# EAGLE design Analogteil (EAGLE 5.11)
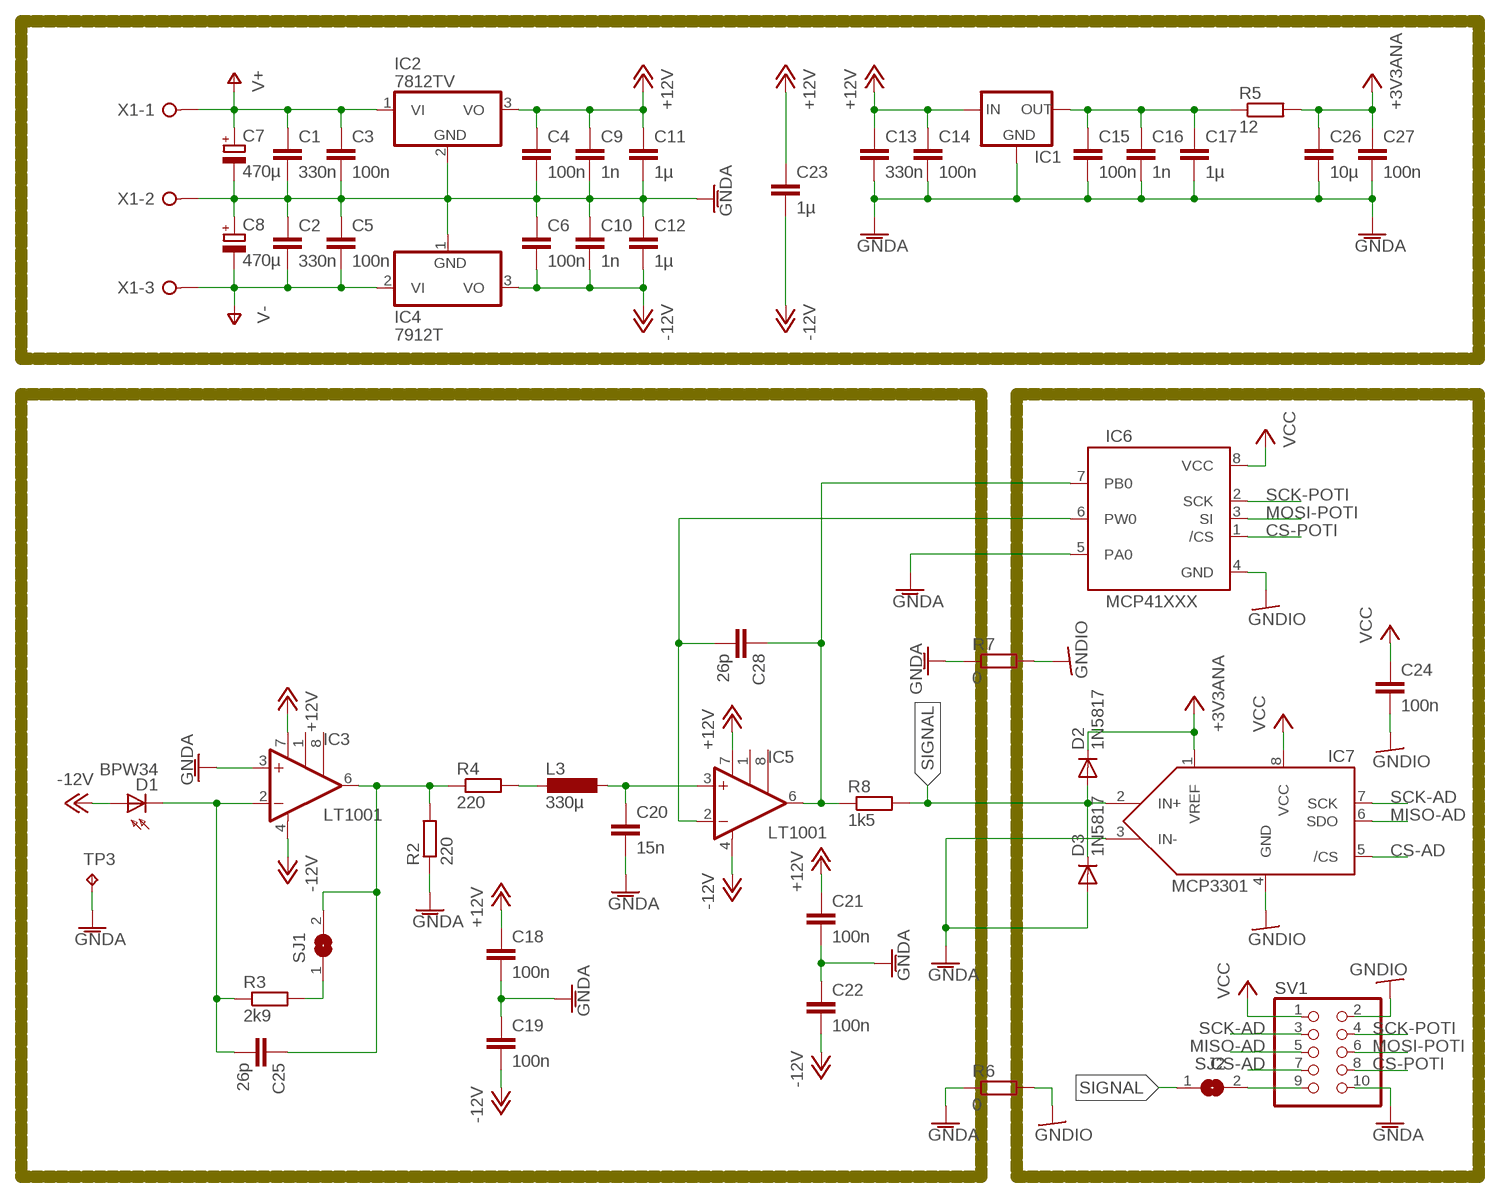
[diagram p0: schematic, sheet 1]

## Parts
C1  330n  C-EU025-024X044  [C025-024X044]
C2  330n  C-EU025-024X044  [C025-024X044]
C3  100n  C-EU025-024X044  [C025-024X044]
C4  100n  C-EU025-024X044  [C025-024X044]
C5  100n  C-EU025-024X044  [C025-024X044]
C6  100n  C-EU025-024X044  [C025-024X044]
C7  470µ  CPOL-EUE3.5-8  [E3,5-8]
C8  470µ  CPOL-EUE3.5-8  [E3,5-8]
C9  1n  C-EU025-024X044  [C025-024X044]
C10  1n  C-EU025-024X044  [C025-024X044]
C11  1µ  C-EU025-024X044  [C025-024X044]
C12  1µ  C-EU025-024X044  [C025-024X044]
C13  330n  C-EU025-024X044  [C025-024X044]
C14  100n  C-EU025-024X044  [C025-024X044]
C15  100n  C-EU025-024X044  [C025-024X044]
C16  1n  C-EU025-024X044  [C025-024X044]
C17  1µ  C-EU025-024X044  [C025-024X044]
C18  100n  C-EU025-024X044  [C025-024X044]
C19  100n  C-EU025-024X044  [C025-024X044]
C20  15n  C-EU025-024X044  [C025-024X044]
C21  100n  C-EU025-024X044  [C025-024X044]
C22  100n  C-EU025-024X044  [C025-024X044]
C23  1µ  C-EU025-024X044  [C025-024X044]
C24  100n  C-EU025-024X044  [C025-024X044]
C25  26p  C-EU025-024X044  [C025-024X044]
C26  10µ  C-EU025-024X044  [C025-024X044]
C27  100n  C-EU025-024X044  [C025-024X044]
C28  26p  C-EU025-024X044  [C025-024X044]
D1  BPW34  BPW32  [BPW32]
D2  1N5817  DIODE-D-2.5  [D-2.5]
D3  1N5817  DIODE-D-2.5  [D-2.5]
IC1  78LXX  [78LXX]
IC2  7812TV  [TO220V]
IC3  LT1001  [DIL08]
IC4  7912T  7912TV  [TO220V]
IC5  LT1001  [DIL08]
IC6  MCP41XXX  [DIL08]
IC7  MCP3301  [DIL08]
L3  330µ  L-EU0204/5  [0204/5]
R2  220  R-EU_0204/2V  [0204V]
R3  2k9  R-EU_0204/2V  [0204V]
R4  220  R-EU_0204/5  [0204/5]
R5  12  R-EU_0204/7  [0204/7]
R6  0  R-EU_0204/2V  [0204V]
R7  0  R-EU_0204/5  [0204/5]
R8  1k5  R-EU_0204/2V  [0204V]
SJ1  SJ  [SJ]
SJ2  SJ  [SJ]
SV1  PINHD-2X05_2.54  [2X05]
TP3  TPPAD1-13  [P1-13]
X1  W237-3E  [W237-3E]

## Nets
+3V3: C26.1 C27.1 D2.C IC7.1(VREF) R5.2 ; supply symbol labelled +3V3ANA
+12V: C4.1 C9.1 C11.1 C13.1 C14.1 C18.1 C21.1 C23.1 IC1.IN IC2.3(VO) IC3.7(V+) IC5.7(V+)
-12V: C6.2 C10.2 C12.2 C19.2 C22.2 C23.2 D1.A IC3.4(V-) IC4.3(VO) IC5.4(V-)
CS-AD: IC7.5(/CS) SV1.7
CS-POTI: IC6.1(/CS) SV1.8
GNDA: C1.2 C2.1 C3.2 C4.2 C5.1 C6.1 C7.- C8.+ C9.2 C10.1 C11.2 C12.1 C13.2 C14.2 C15.2 C16.2 C17.2 C18.2 C19.1 C20.2 C21.2 C22.1 C26.2 C27.2 D3.A IC1.GND IC2.2(GND) IC3.3(+IN) IC4.1(GND) IC6.5(PA0) IC7.3(IN-) R2.1 R6.1 R7.1 SV1.10 TP3.TP X1.2
GNDIO: C24.2 IC6.4(GND) IC7.4(GND) R6.2 R7.2 SV1.2
MISO-AD: IC7.6(SDO) SV1.5
MOSI-POTI: IC6.3(SI) SV1.6
N$1: R3.2 SJ1.1
N$3: SJ2.2 SV1.9
N$6: C25.2 D1.K(C) IC3.2(-IN) R3.1
N$7: C25.1 IC3.6(OUT) R2.2 R4.1 SJ1.2
N$8: L3.2 R4.2
N$9: C20.1 IC5.3(+IN) L3.1
N$10: C28.2 IC5.2(-IN) IC6.6(PW0)
N$11: C15.1 C16.1 C17.1 IC1.OUT R5.1
N$12: C28.1 IC5.6(OUT) IC6.7(PB0) R8.1
SCK-AD: IC7.7(SCK) SV1.3
SCK-POTI: IC6.2(SCK) SV1.4
SIGNAL: D2.A D3.C IC7.2(IN+) R8.2 SJ2.1
V+: C1.1 C3.1 C7.+ IC2.1(VI) X1.1
V-: C2.2 C5.2 C8.- IC4.2(VI) X1.3
VCC: C24.1 IC6.8(VCC) IC7.8(VCC) SV1.1
Unconnected: IC3.1(VOS1) IC3.8(VOS2) IC5.1(VOS1) IC5.8(VOS2)

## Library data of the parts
C1-C6 C9-C27 = resistor:C-EU: CAPACITOR, European symbol
C7 C8 = resistor:CPOL-EU: POLARIZED CAPACITOR, European symbol
C28 = _rcl:C-EU: CAPACITOR, European symbol
D1 = opto-trans-siemens:BPW32: PHOTO DIODE; OC_FARNELL: unknown; OC_NEWARK: unknown
D2 D3 = _mod_diode:DIODE-: DIODE
IC1 = v-reg:78LXX: VOLTAGE REGULATOR
IC2 = linear:78*: Positive VOLTAGE REGULATOR Source: http://cache.national.com/ds/LM/LM78L05.pdf http://www.fairchildsemi.com/ds/LM/LM7805.pdf
IC3 IC5 = _LT100_:LT1001
IC4 = linear:79*: Negative VOLTAGE REGULATOR
IC6 = _LT100_:MCP41XXX
IC7 = _LT100_:MCP3301
L3 = resistor:L-EU: INDUCTOR, European symbol
R2 R5 R7 = resistor:R-EU_: RESISTOR, European symbol
R3 R4 R6 R8 = _rcl:R-EU_: RESISTOR, European symbol
SJ1 SJ2 = jumper:SJ: SMD solder JUMPER
SV1 = _pinhead-2:PINHD-2X05: PIN HEADER
TP3 = testpad:TP: Test pad
X1 = con-wago-508:W237-3E: WAGO SREW CLAMP; OC_FARNELL: unknown; OC_NEWARK: unknown

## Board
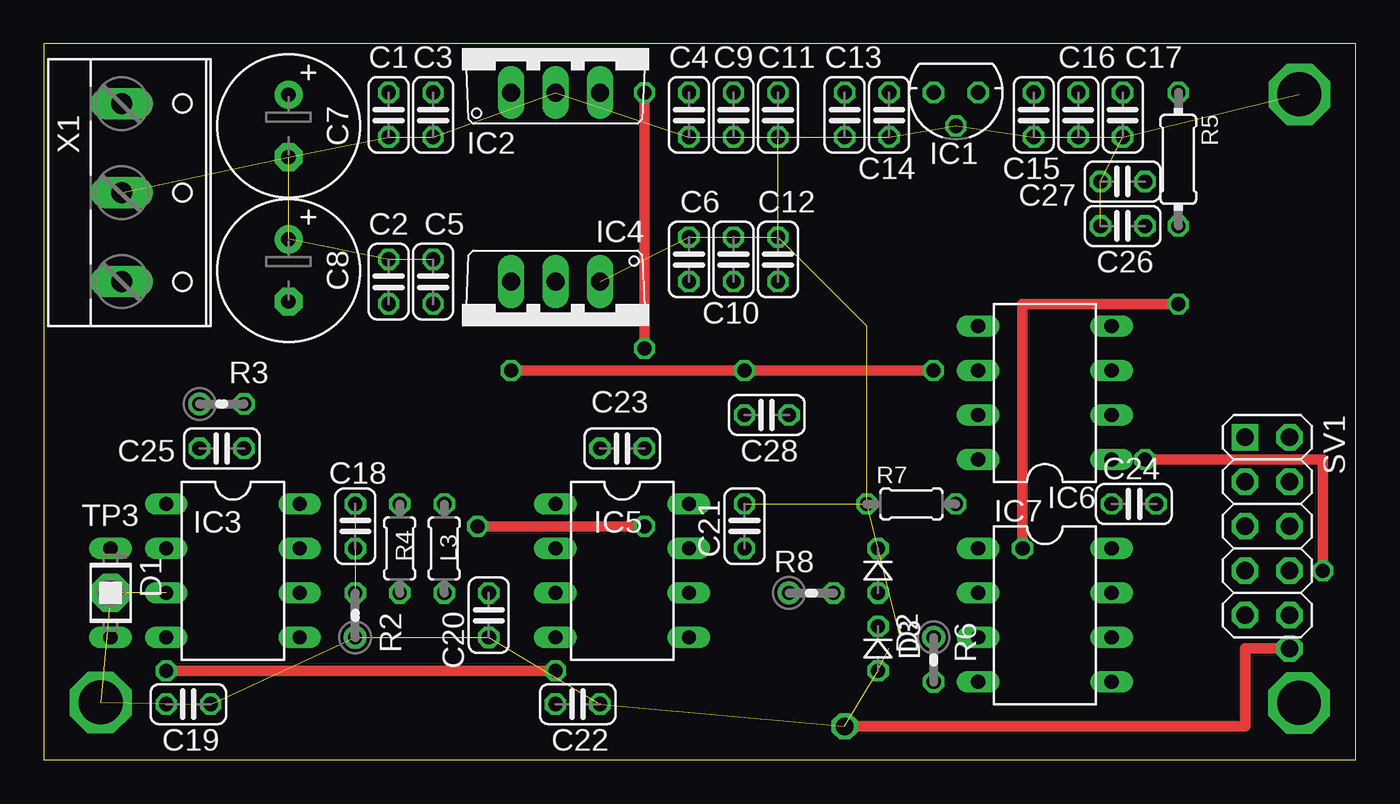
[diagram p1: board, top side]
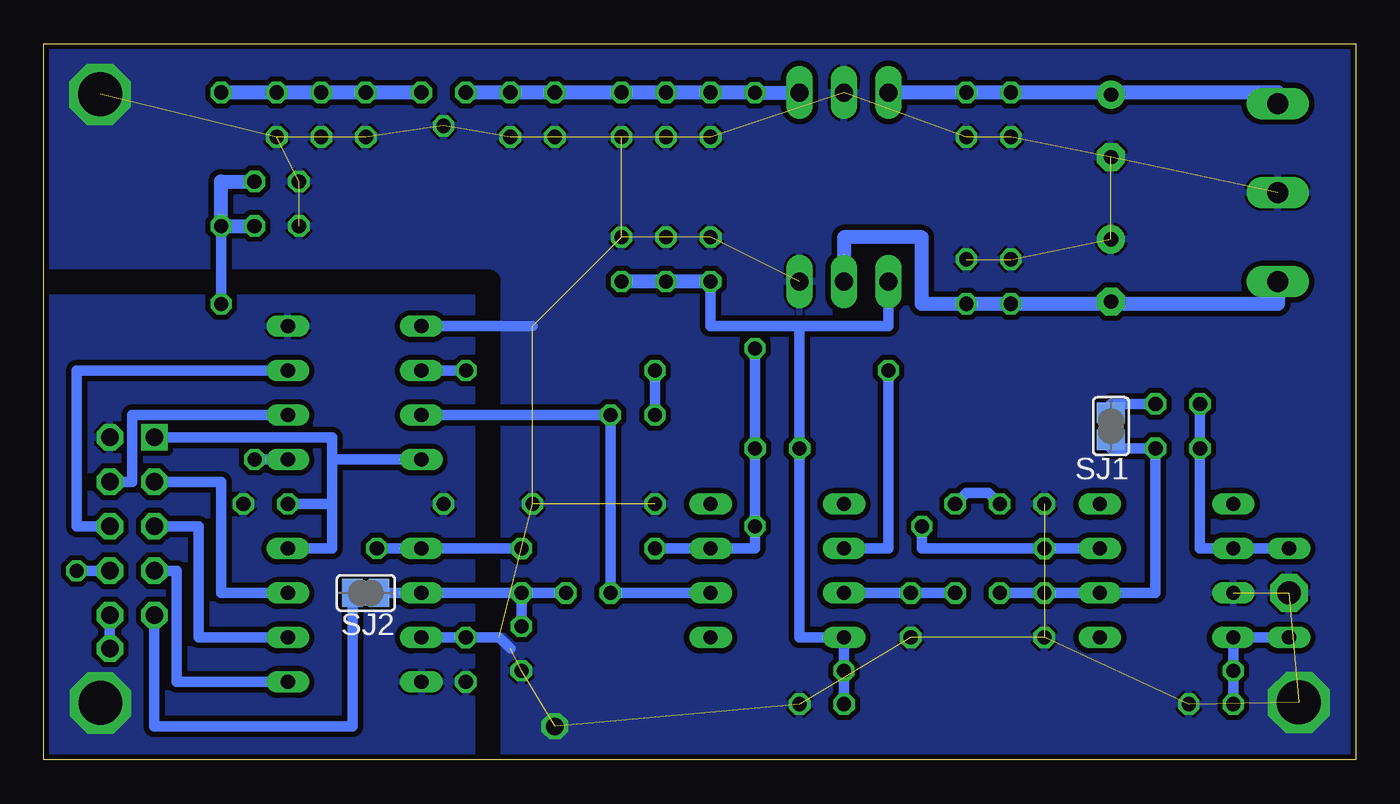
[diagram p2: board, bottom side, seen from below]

Size 74.89 x 40.88 mm. Coordinates in mm from the lower left corner, seen from the top.
Outline: 0,0 74.89,0 74.89,40.87 74.89,40.88 0,40.88 0,0
Copper layers (1*16): Top 0.035mm / dielectric 1.5mm / Bottom 0.035mm
Design rules "default": minimum track width 0.15mm, minimum drill 0.3mm, track to track 0.15mm, track to pad 0.15mm, pad to pad 0.15mm, via to via 0.15mm, smd to smd 0mil, copper to edge 0.2mm, drill to drill 0.2mm, minimum pad ring 0.2mm, minimum via ring 0.2mm, stop-mask expansion 4mil, vias tented up to drill 0.8mm, thermal gap 0.15mm
bRestrict: 2 lines

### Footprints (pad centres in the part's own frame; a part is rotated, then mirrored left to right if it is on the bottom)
C025-024X044 = drill 0.813 octagon: 1 -1.27,0; 2 1.27,0
E3,5-8 = drill 0.813 pad 1.6 round: + -1.778,0 | drill 0.813 pad 1.6 octagon: - 1.778,0
BPW32 = drill 0.813 long: A 0,2.54; K 0,-2.54
D-2.5 = drill 0.813 octagon: A 1.27,0; C -1.27,0
78LXX = drill 0.813 octagon: GND 0,1.905; IN 1.27,0; OUT -1.27,0
TO220V = drill 1.016 long: 1 -2.54,-2.54; 2 0,-2.54; 3 2.54,-2.54
DIL08 = drill 0.813 long: 1 -2.54,-3.81; 2 0,-3.81; 3 2.54,-3.81; 4 5.08,-3.81; 5 5.08,3.81; 6 2.54,3.81; 7 0,3.81; 8 -2.54,3.81
0204/5 = drill 0.813 octagon: 1 -2.54,0; 2 2.54,0
0204V = drill 0.813 octagon: 1 -1.27,0; 2 1.27,0
0204/7 = drill 0.813 octagon: 1 -3.81,0; 2 3.81,0
SJ = smd 1.168 x 1.6: 1 -0.762,0; 2 0.762,0
2X05 = drill 1.016 square: 1 -5.08,-1.27 | drill 1.016 octagon: 2 -5.08,1.27; 3 -2.54,-1.27; 4 -2.54,1.27; 5 0,-1.27; 6 0,1.27; 7 2.54,-1.27; 8 2.54,1.27; 9 5.08,-1.27; 10 5.08,1.27
P1-13 = drill 1.321 pad 2.159 octagon: TP 0,0
W237-3E = drill 1.194 long: 1 -5.08,-0.635; 2 0,-0.635; 3 5.08,-0.635

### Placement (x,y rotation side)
C1  19.68,36.83 270 top
C2  19.68,27.3 270 top
C3  22.23,36.83 270 top
C4  36.83,36.83 270 top
C5  22.23,27.3 270 top
C6  36.83,28.57 270 top
C7  13.97,36.2 270 top
C8  13.97,27.94 270 top
C9  39.37,36.83 270 top
C10  39.37,28.57 270 top
C11  41.91,36.83 270 top
C12  41.91,28.57 270 top
C13  45.72,36.83 270 top
C14  48.26,36.83 270 top
C15  56.52,36.83 270 top
C16  59.05,36.83 270 top
C17  61.59,36.83 270 top
C18  17.78,13.34 90 top
C19  8.26,3.17 180 top
C20  25.4,8.26 270 top
C21  40.01,13.34 90 top
C22  30.48,3.17 180 top
C23  33.02,17.78 180 top
C24  62.23,14.61 0 top
C25  10.16,17.78 180 top
C26  61.59,30.48 180 top
C27  61.59,33.02 180 top
C28  41.27,19.68 180 top
D1  3.81,9.53 180 top
D2  47.62,10.79 270 top
D3  47.62,6.35 270 top
IC1  52.07,38.1 180 top
IC2  29.21,40.64 0 top
IC3  10.79,12.06 270 top
IC4  29.21,24.77 180 top
IC5  33.02,12.06 270 top
IC6  57.15,19.68 90 top
IC7  57.15,9.53 270 top
L3  22.86,12.06 90 top
R2  17.78,8.26 90 top
R3  10.16,20.32 0 top
R4  20.32,12.06 90 top
R5  64.77,34.29 270 top
R6  50.8,5.71 270 top
R7  49.53,14.61 0 top
R8  43.81,9.53 0 top
SJ1  13.97,19.05 270 bottom
SJ2  56.52,9.53 180 bottom
SV1  69.85,13.34 270 top
TP3  3.81,9.53 270 top
X1  5.08,32.38 270 top

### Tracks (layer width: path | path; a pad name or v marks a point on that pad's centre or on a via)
+3V3  (via drill 0.8)
  Top 0.61: v55.88,12.06 55.88,26.04 v64.77,26.04
  Bottom 0.61: D2.C IC7.1 v55.88,12.06 | v64.77,26.04 R5.2
  Bottom 0.813: C26.1 R5.2 64.77,33.02 C27.1
+12V  (via drill 0.8)
  Top 0.61: v34.29,23.5 v34.29,38.1 | v24.77,13.34 v34.29,13.34
  Bottom 0.61: C18.1 IC3.7 24.77,12.06 v24.77,13.34 | C21.1 IC5.7 34.29,12.06 v34.29,13.34 C23.1 v34.29,23.5
  Bottom 0.813: IC2.3 v34.29,38.1 C4.1 C9.1 C11.1 C13.1 C14.1 IC1.IN
-12V  (via drill 0.8)
  Top 0.61: v6.99,5.08 v29.21,5.08
  Bottom 0.61: D1.A IC3.4 v6.99,5.08 C19.2 | C6.2 36.83,24.77 31.75,24.77 | 31.75,24.77 26.67,24.77 IC4.3 | C22.2 v29.21,5.08 IC5.4 31.75,6.99 C23.2 31.75,24.77
  Bottom 0.813: C6.2 C10.2 C12.2
CS-AD
  Bottom 0.61: SV1.7 67.31,10.79 67.31,4.45 IC7.5
CS-POTI  (via drill 0.8)
  Top 0.61: v73.03,10.79 73.03,17.14 v62.87,17.14
  Bottom 0.61: IC6.1 v62.87,17.14 | v73.03,10.79 SV1.8
GNDA  (via drill 1, 2.5)  (37 unrouted)
  Top 0.61: v45.72,1.91 68.58,1.91 68.58,6.35 v71.12,6.35
  Bottom 0.61: IC7.3 R6.1 48.9,6.99 48.26,6.35 | 46.99,24.77 IC6.5 | v71.12,6.35 SV1.10
  other vias: 71.68,38 3.25,3.27
  pour Bottom (isolate 0.305): 0,0 0,40.9 74.89,40.9 74.89,27.94 49.15,27.94 arc90 48.9,27.69 48.9,0
GNDIO  (via drill 2.5)
  other vias: 71.66,3.25
  pour Bottom (isolate 0.305): 50.16,26.67 74.89,26.67 74.89,0 50.16,0
MISO-AD
  Bottom 0.61: IC7.6 66.04,6.99 66.04,13.34 SV1.5
MOSI-POTI
  Bottom 0.61: SV1.6 73.03,13.34 73.03,22.23 IC6.3
N$1
  Bottom 0.61: R3.2 13.97,20.32 SJ1.1
N$3
  Bottom 0.61: SV1.9 68.58,1.91 57.28,1.91 SJ2.2
N$6
  Bottom 0.61: IC3.2 D1.K 8.89,12.06 R3.1 C25.2
N$7
  Bottom 0.61: R2.2 R4.1 IC3.6 11.43,9.53 C25.1 13.97,17.78 SJ1.2
N$8
  Bottom 0.61: R4.2 20.95,15.24 22.23,15.24 L3.2
N$9
  Bottom 0.61: C20.1 L3.1 IC5.3
N$10  (via drill 0.8)
  Top 0.61: v26.67,22.23 v40.01,22.23 v50.8,22.23
  Bottom 0.61: IC5.2 26.67,12.06 v26.67,22.23 | v50.8,22.23 IC6.6 | v40.01,22.23 C28.2
N$11
  Bottom 0.813: R5.1 C17.1 C16.1 C15.1 IC1.OUT
N$12
  Bottom 0.61: IC6.7 C28.1 R8.1 IC5.6
SCK-AD
  Bottom 0.61: SV1.3 64.77,15.88 64.77,9.53 IC7.7
SCK-POTI
  Bottom 0.61: IC6.2 69.85,19.68 69.85,15.88 SV1.4
SIGNAL
  Bottom 0.61: D2.A IC7.2 SJ2.1 | D2.A D3.C | R8.2 D2.A
V+
  Bottom 0.813: 13.97,38.1 C1.1 C3.1 IC2.1 | 13.97,38.1 C7.+ | 13.97,38.1 4.45,38.1 X1.1
V-
  Bottom 0.813: IC4.2 29.21,29.84 24.77,29.84 24.77,26.04 C5.2 C2.2 13.97,26.04 | 13.97,26.04 C8.- | 13.97,26.04 4.45,26.04 X1.3
VCC
  Bottom 0.61: 58.42,14.61 58.42,12.06 IC7.8 | 58.42,14.61 C24.1 | 58.42,17.14 58.42,14.61 | IC6.8 58.42,17.14 | SV1.1 58.42,18.41 58.42,17.14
